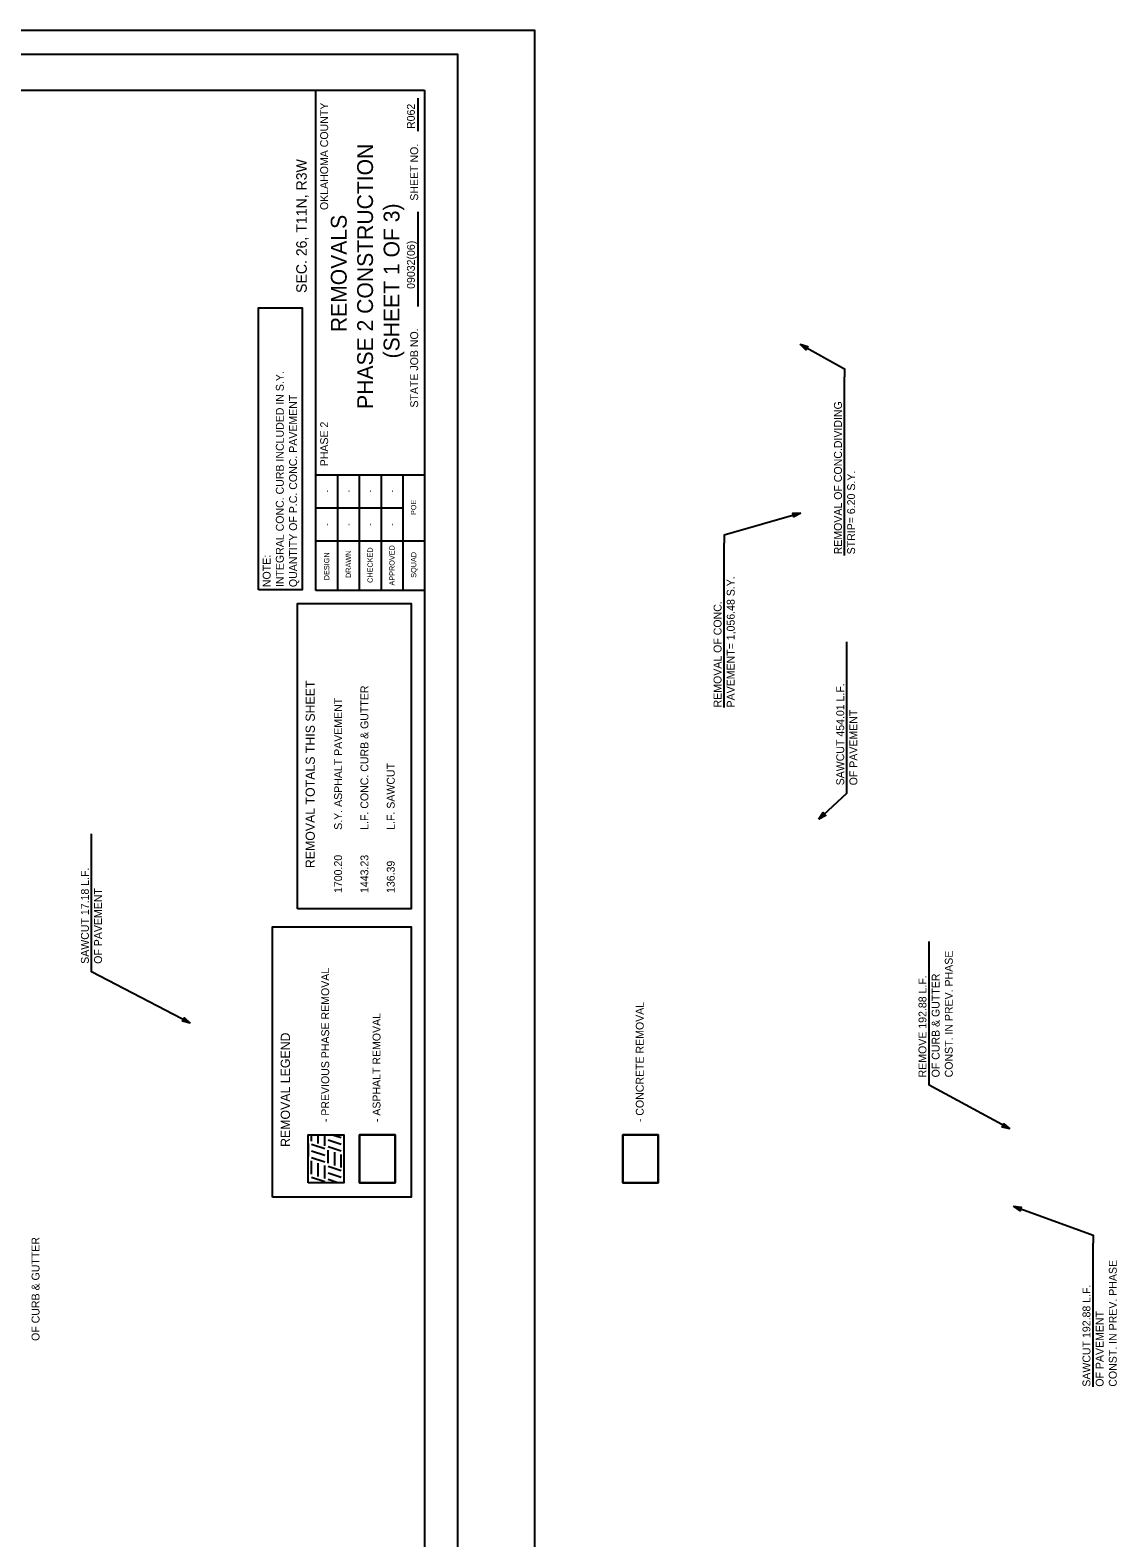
# Model space of a CAD drawing. Extents: x 2150645 to 2152288, y 141590 to 143592.
# Drawn here: x 2151462 to 2152288, y 142447 to 143592 of the extents above; entities that cross this region are included whole.
import ezdxf

# ---------------------------------------------------------------- set-up
doc = ezdxf.new("R2010")
doc.units = 0
for name, color, linetype in [('EX_Align', 7, 'Continuous'), ('INR_InRoads_Unassigned', 7, 'Continuous'), ('PR_Align_Ramp_D', 7, 'Continuous'), ('PR_Pattern_Area_Removal_Asph', 7, 'Continuous'), ('PR_Pattern_Area_Removal_Conc', 7, 'Continuous'), ('PR_Phasing_Pavement_1', 7, 'Continuous'), ('SHT_Standard_Sheet_Lines', 7, 'Continuous'), ('SHT_Standard_Sheet_Txt', 7, 'Continuous'), ('SHT_Title_Sheet_Misc', 7, 'Continuous'), ('TOPO_DRAIN_Headwall', 7, 'Continuous'), ('TOPO_San Manhole', 7, 'Continuous')]:
    doc.layers.add(name, color=color, linetype=linetype)

msp = doc.modelspace()

# ---------------------------------------------------------------- linework, layer by layer
at = {"layer": 'EX_Align'}
msp.add_lwpolyline([(2150645.3, 141792.1), (2150645.3, 143592.1), (2151845.3, 143592.1), (2151845.3, 141792.1)], close=True, dxfattribs=at)
at = {"layer": 'PR_Align_Ramp_D'}
for p, q in [((2151679.1, 143166.4), (2151679.1, 143546.4)), ((2151761.6, 143253.9), (2151679, 143253.9)), ((2151761.6, 143166.4), (2151679.1, 143166.4))]:
    msp.add_line(p, q, dxfattribs=at)
msp.add_lwpolyline([(2151761.6, 143546.4), (2151761.6, 141971.4), (2150711.6, 141971.4), (2150711.6, 143546.4)], close=True, dxfattribs=at)
at = {"layer": 'PR_Pattern_Area_Removal_Asph'}
msp.add_lwpolyline([(2151739.3, 142716.2), (2151739.3, 142752.8), (2151712.3, 142752.8), (2151712.3, 142716.2), (2151739.3, 142716.2)], dxfattribs=at)
at = {"layer": 'PR_Pattern_Area_Removal_Conc'}
for p, q in [((2151673.4, 142736.2), (2151673.4, 142746.2)), ((2151675.9, 142747.9), (2151675.9, 142752.8)), ((2151685.8, 142742.1), (2151675.9, 142745.4)), ((2151680.9, 142746.2), (2151680.9, 142752.8)), ((2151685.9, 142744.5), (2151685.9, 142752.8)), ((2151698.4, 142740.4), (2151688.4, 142743.7)), ((2151698.4, 142745.4), (2151688.5, 142748.7)), ((2151698.4, 142750.4), (2151691, 142752.8)), ((2151685.8, 142737.1), (2151675.9, 142740.4)), ((2151685.8, 142732.1), (2151675.9, 142735.4)), ((2151675.9, 142722.9), (2151675.9, 142732.9)), ((2151680.9, 142721.2), (2151680.9, 142731.2)), ((2151688.4, 142731.2), (2151688.4, 142741.2)), ((2151693.4, 142729.5), (2151693.4, 142739.5)), ((2151698.4, 142727.9), (2151698.4, 142737.9)), ((2151673.3, 142716.2), (2151673.3, 142721.2)), ((2151685.8, 142717.1), (2151675.9, 142720.4)), ((2151685.9, 142719.5), (2151685.9, 142729.5)), ((2151698.4, 142725.4), (2151688.4, 142728.7)), ((2151698.4, 142720.4), (2151688.4, 142723.7)), ((2151695.9, 142716.2), (2151688.4, 142718.7))]:
    msp.add_line(p, q, dxfattribs=at)
msp.add_lwpolyline([(2151939.3, 142716.2), (2151939.3, 142752.8), (2151912.3, 142752.8), (2151912.3, 142716.2), (2151939.3, 142716.2)], dxfattribs=at)
at = {"layer": 'SHT_Standard_Sheet_Lines'}
for p, q in [((2151756.8, 143515.2), (2151756.8, 143540.3)), ((2151756.8, 143382), (2151756.8, 143454)), ((2151745.1, 143228.9), (2151679, 143228.9)), ((2151761.6, 143203.9), (2151679, 143203.9))]:
    msp.add_line(p, q, dxfattribs=at)
for points in [[(2151695.6, 143253.9), (2151695.6, 143166.4)], [(2151712.1, 143253.9), (2151712.1, 143166.4)], [(2151728.6, 143253.9), (2151728.6, 143166.4)], [(2151745.1, 143253.9), (2151745.1, 143166.4)]]:
    msp.add_lwpolyline(points, dxfattribs=at)
at = {"layer": 'SHT_Title_Sheet_Misc'}
for points in [[(2151635.6, 143166.9), (2151635.6, 143381), (2151668.7, 143381), (2151668.7, 143166.9)], [(2151665.2, 142924.5), (2151665.2, 143156.4), (2151751.6, 143156.4), (2151751.6, 142924.5)], [(2151646.1, 142705.4), (2151646.1, 142910.8), (2151751.6, 142910.8), (2151751.6, 142705.4)], [(2151673.3, 142716.2), (2151673.3, 142752.8), (2151700.3, 142752.8), (2151700.3, 142716.2)], [(2151712.3, 142716.2), (2151712.3, 142752.8), (2151739.3, 142752.8), (2151739.3, 142716.2)], [(2151912.3, 142716.2), (2151912.3, 142752.8), (2151939.3, 142752.8), (2151939.3, 142716.2)]]:
    msp.add_lwpolyline(points, close=True, dxfattribs=at)
at = {"layer": 'TOPO_DRAIN_Headwall'}
msp.add_lwpolyline([(2150686.6, 141873.9), (2150686.6, 143573.9), (2151786.6, 143573.9), (2151786.6, 141873.9)], close=True, dxfattribs=at)
at = {"layer": 'TOPO_San Manhole'}
for p, q in [((2152080.8, 143192.9), (2152080.8, 143328.8)), ((2151989.3, 143077.5), (2151989.3, 143202.3)), ((2152082.5, 143018.3), (2152082.5, 143127.3)), ((2151508.6, 142882.7), (2151508.6, 142981.5)), ((2152145, 142796.4), (2152145, 142899.6)), ((2152269.6, 142561.4), (2152269.6, 142670.5))]:
    msp.add_line(p, q, dxfattribs=at)
for points in [[(2152047.1, 143353.4), (2152080.8, 143334.8), (2152080.8, 143328.8)], [(2152047.5, 143225.2), (2151989.3, 143208.3), (2151989.3, 143202.3)], [(2152061.2, 142992.6), (2152082.5, 143012.3), (2152082.5, 143018.3)], [(2151583.7, 142837.7), (2151508.6, 142876.7), (2151508.6, 142882.7)], [(2152206.3, 142757.2), (2152145, 142790.4), (2152145, 142796.4)], [(2152209.2, 142698.5), (2152269.6, 142676.5), (2152269.6, 142670.5)]]:
    msp.add_lwpolyline(points, dxfattribs=at)
for points in [[(2152047.1, 143353.4), (2152052.9, 143351.8), (2152051.5, 143349.3)], [(2152047.5, 143225.2), (2152042.3, 143222.2), (2152041.5, 143225)], [(2152061.2, 142992.6), (2152064.5, 142997.7), (2152066.5, 142995.5)], [(2151583.7, 142837.7), (2151577.8, 142839.1), (2151579.2, 142841.7)], [(2152206.3, 142757.2), (2152200.5, 142758.7), (2152201.9, 142761.2)], [(2152209.2, 142698.5), (2152215.1, 142697.9), (2152214.1, 142695.1)]]:
    msp.add_lwpolyline(points, close=True, dxfattribs=at)

# ---------------------------------------------------------------- texts
at = {"layer": 'INR_InRoads_Unassigned'}
msp.add_text('SEC. 26, T11N, R3W', height=8, rotation=90.027, dxfattribs=at).set_placement((2151672.2, 143392.4))
at = {"layer": 'PR_Phasing_Pavement_1'}
for s, p in [('INTEGRAL CONC. CURB INCLUDED IN S.Y.', (2151654.7, 143168.9)), ('QUANTITY OF P.C. CONC. PAVEMENT', (2151664.8, 143168.9)), ('NOTE:', (2151644.7, 143168.9))]:
    msp.add_text(s, height=6, rotation=90, dxfattribs=at).set_placement(p)
at = {"layer": 'SHT_Standard_Sheet_Txt'}
for s, height, p in [('OKLAHOMA COUNTY', 6, (2151688.4, 143455.4)), ('R062', 6, (2151754.3, 143517)), ('PHASE 2 CONSTRUCTION', 12, (2151722.5, 143304.3)), ('SHEET NO. ', 6, (2151756.8, 143462.5)), ('(SHEET 1 OF 3)', 12, (2151742.6, 143342.7)), ('REMOVALS', 12, (2151702.5, 143362.6)), ('09032(06)', 6, (2151754.3, 143395.5)), ('STATE JOB NO.', 6, (2151756.8, 143305.3)), ('PHASE 2', 6, (2151688.4, 143260.7)), ('-', 4, (2151689.3, 143240.9)), ('-', 4, (2151705.8, 143240.9)), ('-', 4, (2151722.3, 143240.9)), ('-', 4, (2151738.8, 143240.9)), ('POE', 4, (2151755.3, 143223.7)), ('-', 4, (2151689.3, 143215.5)), ('-', 4, (2151705.8, 143215.5)), ('-', 4, (2151722.3, 143215.5)), ('-', 4, (2151738.8, 143215.5)), ('DESIGN', 4, (2151689.3, 143174.1)), ('DRAWN', 4, (2151705.8, 143175.8)), ('CHECKED', 4, (2151722.3, 143172.1)), ('APPROVED', 4, (2151738.9, 143170.1)), ('SQUAD', 4, (2151755.4, 143176))]:
    msp.add_text(s, height=height, rotation=90, dxfattribs=at).set_placement(p)
at = {"layer": 'TOPO_San Manhole'}
for s, height, p in [('REMOVAL OF CONC.DIVIDING', 6, (2152078.8, 143193.8)), ('STRIP= 6.20 S.Y.', 6, (2152088.8, 143193.8)), ('PAVEMENT= 1,056.48 S.Y.', 6, (2151997.3, 143077.5)), ('REMOVAL OF CONC.', 6, (2151987.3, 143077.5)), ('REMOVAL TOTALS THIS SHEET', 7, (2151678.3, 142955.4)), ('L.F. CONC. CURB & GUTTER', 6, (2151719, 142984.5)), ('SAWCUT 454.01 L.F. ', 6, (2152080.5, 143018.3)), ('S.Y. ASPHALT PAVEMENT', 6, (2151699, 142984.5)), ('OF PAVEMENT', 6, (2152090.5, 143018.3)), ('L.F. SAWCUT', 6, (2151739, 142984.5)), ('1700.20', 6, (2151699, 142936.5)), ('1443.23', 6, (2151719, 142936.5)), ('136.39', 6, (2151739, 142936.5)), ('SAWCUT 17.18 L.F. ', 6, (2151506.6, 142882.7)), ('OF PAVEMENT', 6, (2151516.6, 142882.7)), ('CONST. IN PREV. PHASE', 6, (2152163, 142796.4)), ('- PREVIOUS PHASE REMOVAL', 6, (2151689.2, 142762.4)), ('REMOVE 192.88 L.F.', 6, (2152143, 142796.4)), ('OF CURB & GUTTER', 6, (2152153, 142796.4)), ('- CONCRETE REMOVAL', 6, (2151928.2, 142762.4)), ('- ASPHALT REMOVAL', 6, (2151728.2, 142762.4)), ('REMOVAL LEGEND', 7, (2151659.4, 142743.6)), ('OF CURB & GUTTER', 6, (2151469.1, 142596.2)), ('CONST. IN PREV. PHASE', 6, (2152287.6, 142561.4)), ('SAWCUT 192.88 L.F. ', 6, (2152267.6, 142561.4)), ('OF PAVEMENT', 6, (2152277.6, 142561.4))]:
    msp.add_text(s, height=height, rotation=90, dxfattribs=at).set_placement(p)

doc.saveas('drawing.dxf')
